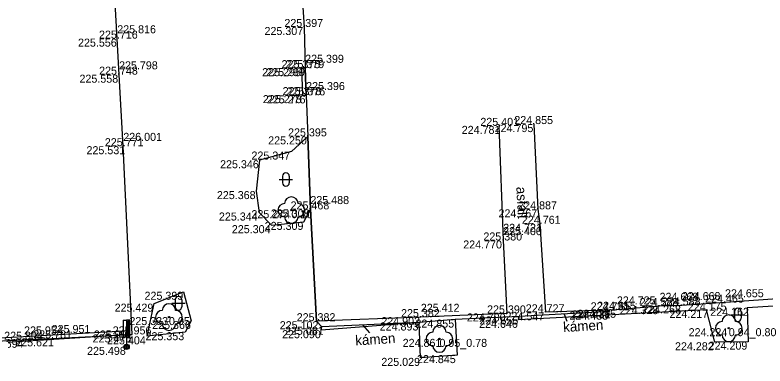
# Model space of a CAD drawing. Extents: x -599516 to -599132, y -1163668 to -1163119.
# Drawn here: x -599371.12 to -599343.03, y -1163301.07 to -1163287.93 of the extents above; entities that cross this region are included whole.
import ezdxf

# ---------------------------------------------------------------- set-up
doc = ezdxf.new("R2010")
doc.units = 0
for name, color, linetype in [('Bod-oznac1', 7, 'Continuous'), ('Bod-oznac2', 7, 'Continuous'), ('Bod-oznac3', 7, 'Continuous'), ('Bod-vyska1', 7, 'Continuous'), ('Bod-vyska2', 7, 'Continuous'), ('Bod-vyska3', 7, 'Continuous'), ('Z_cela-hrobu-dolni-linie', 7, 'Continuous'), ('Z_cela-hrobu-horni-linie', 7, 'Continuous'), ('Z_chodnik', 7, 'Continuous'), ('Z_komunikace', 7, 'Continuous'), ('Z_kultury-znacky', 7, 'Continuous'), ('Z_nove-stromy-prumer-kmene', 7, 'Continuous'), ('Z_obvod-kmene-spodek-ve-vysce1_2m', 7, 'Continuous'), ('Z_ploty-drateny-kovovy', 7, 'Continuous'), ('Z_popis-budov-povrchu', 7, 'Continuous'), ('Z_stromy-kere', 7, 'Continuous'), ('Z_stromy-nove-vysazene', 7, 'Continuous'), ('Z_vol-lin-odkazova-cara', 7, 'Continuous'), ('Z_znacky-ostatni-orientacni-sloupek', 7, 'Continuous'), ('Z_zpevnene-plochy', 7, 'Continuous')]:
    doc.layers.add(name, color=color, linetype=linetype)

msp = doc.modelspace()

# ---------------------------------------------------------------- linework, layer by layer
at = {"layer": 'Bod-oznac1'}
for p, q in [((-599360.296, -1163288.376), (-599360.296, -1163288.376)), ((-599367.294, -1163288.811), (-599367.294, -1163288.811)), ((-599360.396, -1163289.918), (-599360.396, -1163289.918)), ((-599360.254, -1163289.915), (-599360.254, -1163289.915)), ((-599367.227, -1163290.162), (-599367.227, -1163290.162)), ((-599360.357, -1163290.928), (-599360.357, -1163290.928)), ((-599360.217, -1163290.938), (-599360.217, -1163290.938)), ((-599351.672, -1163292.012), (-599351.672, -1163292.012)), ((-599352.997, -1163292.079), (-599352.997, -1163292.079)), ((-599360.159, -1163292.473), (-599360.159, -1163292.473)), ((-599367.068, -1163292.841), (-599367.068, -1163292.841)), ((-599360.77, -1163293.041), (-599360.77, -1163293.041)), ((-599361.959, -1163293.366), (-599361.959, -1163293.366)), ((-599362.091, -1163294.522), (-599362.091, -1163294.522)), ((-599361.981, -1163295.324), (-599361.981, -1163295.324)), ((-599360.772, -1163295.237), (-599360.772, -1163295.237)), ((-599360.059, -1163295.208), (-599360.059, -1163295.208)), ((-599351.524, -1163295.205), (-599351.524, -1163295.205)), ((-599361.51, -1163295.798), (-599361.51, -1163295.798)), ((-599360.301, -1163295.675), (-599360.301, -1163295.675)), ((-599351.443, -1163295.747), (-599351.443, -1163295.747)), ((-599352.836, -1163296.372), (-599352.836, -1163296.372)), ((-599364.813, -1163298.292), (-599364.813, -1163298.292)), ((-599365.91, -1163298.738), (-599365.91, -1163298.738)), ((-599344.524, -1163298.699), (-599344.524, -1163298.699)), ((-599348.862, -1163298.988), (-599348.862, -1163298.988)), ((-599348.848, -1163299.036), (-599348.848, -1163299.036)), ((-599348.575, -1163298.967), (-599348.575, -1163298.967)), ((-599346.976, -1163298.831), (-599346.976, -1163298.831)), ((-599346.144, -1163298.805), (-599346.144, -1163298.805)), ((-599345.212, -1163298.972), (-599345.212, -1163298.972)), ((-599343.698, -1163298.893), (-599343.698, -1163298.893)), ((-599365.357, -1163299.241), (-599365.357, -1163299.241)), ((-599355.921, -1163299.244), (-599355.921, -1163299.244)), ((-599352.704, -1163299.104), (-599352.704, -1163299.104)), ((-599352.237, -1163299.217), (-599352.237, -1163299.217)), ((-599351.241, -1163299.062), (-599351.241, -1163299.062)), ((-599364.526, -1163299.386), (-599364.526, -1163299.386)), ((-599359.83, -1163299.396), (-599359.83, -1163299.396)), ((-599355.98, -1163299.444), (-599355.98, -1163299.444)), ((-599354.629, -1163299.334), (-599354.629, -1163299.334)), ((-599352.256, -1163299.345), (-599352.256, -1163299.345)), ((-599366.818, -1163299.743), (-599366.818, -1163299.743)), ((-599364.753, -1163299.807), (-599364.753, -1163299.807)), ((-599359.652, -1163299.733), (-599359.652, -1163299.733)), ((-599359.635, -1163299.604), (-599359.635, -1163299.604)), ((-599344.383, -1163299.657), (-599344.383, -1163299.657)), ((-599370.786, -1163300.091), (-599370.786, -1163300.091)), ((-599369.751, -1163300.038), (-599369.751, -1163300.038)), ((-599366.735, -1163299.89), (-599366.735, -1163299.89)), ((-599366.174, -1163299.962), (-599366.174, -1163299.962)), ((-599355.222, -1163300.057), (-599355.222, -1163300.057)), ((-599343.658, -1163300.162), (-599343.658, -1163300.162)), ((-599366.944, -1163300.356), (-599366.944, -1163300.356)), ((-599344.905, -1163300.184), (-599344.905, -1163300.184)), ((-599354.559, -1163300.665), (-599354.559, -1163300.665)), ((-599355.933, -1163300.769), (-599355.933, -1163300.769))]:
    msp.add_line(p, q, dxfattribs=at)
at = {"layer": 'Bod-oznac2'}
for p, q in [((-599360.296, -1163288.376), (-599360.296, -1163288.376)), ((-599367.294, -1163288.811), (-599367.294, -1163288.811)), ((-599360.396, -1163289.918), (-599360.396, -1163289.918)), ((-599360.254, -1163289.915), (-599360.254, -1163289.915)), ((-599367.227, -1163290.162), (-599367.227, -1163290.162)), ((-599360.357, -1163290.928), (-599360.357, -1163290.928)), ((-599360.217, -1163290.938), (-599360.217, -1163290.938)), ((-599351.672, -1163292.012), (-599351.672, -1163292.012)), ((-599352.997, -1163292.079), (-599352.997, -1163292.079)), ((-599360.159, -1163292.473), (-599360.159, -1163292.473)), ((-599367.068, -1163292.841), (-599367.068, -1163292.841)), ((-599360.059, -1163295.208), (-599360.059, -1163295.208)), ((-599351.524, -1163295.205), (-599351.524, -1163295.205)), ((-599351.443, -1163295.747), (-599351.443, -1163295.747)), ((-599352.836, -1163296.372), (-599352.836, -1163296.372)), ((-599344.524, -1163298.699), (-599344.524, -1163298.699)), ((-599348.862, -1163298.988), (-599348.862, -1163298.988)), ((-599348.575, -1163298.967), (-599348.575, -1163298.967)), ((-599346.976, -1163298.831), (-599346.976, -1163298.831)), ((-599346.144, -1163298.805), (-599346.144, -1163298.805)), ((-599355.921, -1163299.244), (-599355.921, -1163299.244)), ((-599352.704, -1163299.104), (-599352.704, -1163299.104)), ((-599351.241, -1163299.062), (-599351.241, -1163299.062)), ((-599359.83, -1163299.396), (-599359.83, -1163299.396)), ((-599370.786, -1163300.091), (-599370.786, -1163300.091)), ((-599369.751, -1163300.038), (-599369.751, -1163300.038)), ((-599366.735, -1163299.89), (-599366.735, -1163299.89))]:
    msp.add_line(p, q, dxfattribs=at)
at = {"layer": 'Bod-oznac3'}
for p, q in [((-599367.294, -1163288.811), (-599367.294, -1163288.811)), ((-599360.254, -1163289.915), (-599360.254, -1163289.915)), ((-599367.227, -1163290.162), (-599367.227, -1163290.162)), ((-599360.217, -1163290.938), (-599360.217, -1163290.938)), ((-599367.068, -1163292.841), (-599367.068, -1163292.841)), ((-599360.059, -1163295.208), (-599360.059, -1163295.208)), ((-599352.836, -1163296.372), (-599352.836, -1163296.372)), ((-599344.524, -1163298.699), (-599344.524, -1163298.699)), ((-599348.575, -1163298.967), (-599348.575, -1163298.967)), ((-599346.976, -1163298.831), (-599346.976, -1163298.831)), ((-599346.144, -1163298.805), (-599346.144, -1163298.805)), ((-599355.921, -1163299.244), (-599355.921, -1163299.244)), ((-599370.786, -1163300.091), (-599370.786, -1163300.091)), ((-599369.751, -1163300.038), (-599369.751, -1163300.038))]:
    msp.add_line(p, q, dxfattribs=at)
at = {"layer": 'Z_cela-hrobu-dolni-linie'}
for p, q in [((-599360.217, -1163290.938), (-599360.254, -1163289.915)), ((-599360.159, -1163292.473), (-599360.059, -1163295.208))]:
    msp.add_line(p, q, dxfattribs=at)
for points in [[(-599337.716, -1163298.332), (-599339.375, -1163298.388), (-599341.49, -1163298.479), (-599344.524, -1163298.699), (-599346.144, -1163298.805), (-599346.976, -1163298.831), (-599348.575, -1163298.967), (-599348.862, -1163298.988), (-599351.241, -1163299.062)], [(-599352.704, -1163299.104), (-599355.921, -1163299.244), (-599359.83, -1163299.396)], [(-599373.76, -1163300.233), (-599370.786, -1163300.091), (-599369.751, -1163300.038), (-599366.735, -1163299.89)]]:
    msp.add_lwpolyline(points, dxfattribs=at)
at = {"layer": 'Z_cela-hrobu-horni-linie'}
for points in [[(-599358.085, -1163270.661), (-599361.155, -1163270.895), (-599361.023, -1163273.589), (-599361.023, -1163273.589), (-599361.015, -1163274.729), (-599360.959, -1163276.359), (-599360.959, -1163276.359), (-599360.921, -1163277.44), (-599360.896, -1163277.878), (-599360.835, -1163279.003), (-599360.835, -1163279.003), (-599360.708, -1163280.307), (-599360.708, -1163280.307), (-599360.565, -1163282.313), (-599360.565, -1163282.313), (-599360.49, -1163284.342), (-599360.49, -1163284.342), (-599360.437, -1163286.032), (-599360.407, -1163286.681), (-599360.296, -1163288.376), (-599360.254, -1163289.915), (-599360.217, -1163290.938), (-599360.159, -1163292.473)], [(-599367.068, -1163292.841), (-599367.227, -1163290.162), (-599367.227, -1163290.162), (-599367.294, -1163288.811), (-599367.294, -1163288.811), (-599367.368, -1163287.477)], [(-599331.598, -1163290.945), (-599331.449, -1163294.163), (-599331.449, -1163294.163), (-599331.337, -1163296.61), (-599331.161, -1163297.968), (-599333.927, -1163298.115), (-599333.927, -1163298.115), (-599337.716, -1163298.332), (-599337.716, -1163298.332), (-599339.375, -1163298.388), (-599339.375, -1163298.388), (-599341.49, -1163298.479), (-599341.49, -1163298.479), (-599344.524, -1163298.699), (-599344.524, -1163298.699), (-599346.144, -1163298.805), (-599346.144, -1163298.805), (-599346.976, -1163298.831), (-599346.976, -1163298.831), (-599348.575, -1163298.967), (-599348.575, -1163298.967), (-599348.862, -1163298.988), (-599351.241, -1163299.062), (-599351.443, -1163295.747)], [(-599351.524, -1163295.205), (-599351.672, -1163292.012)], [(-599352.997, -1163292.079), (-599352.836, -1163296.372), (-599352.836, -1163296.372)], [(-599352.836, -1163296.372), (-599352.704, -1163299.104), (-599355.921, -1163299.244), (-599355.921, -1163299.244), (-599359.83, -1163299.396), (-599360.059, -1163295.208), (-599360.059, -1163295.208), (-599360.159, -1163292.473)], [(-599374.034, -1163293.287), (-599373.76, -1163300.233), (-599370.786, -1163300.091), (-599370.786, -1163300.091), (-599369.751, -1163300.038), (-599369.751, -1163300.038), (-599366.735, -1163299.89), (-599367.068, -1163292.841), (-599367.068, -1163292.841), (-599367.068, -1163292.841)]]:
    msp.add_lwpolyline(points, dxfattribs=at)
at = {"layer": 'Z_chodnik'}
for points in [[(-599351.241, -1163299.062), (-599351.443, -1163295.747), (-599351.524, -1163295.205), (-599351.672, -1163292.012)], [(-599352.997, -1163292.079), (-599352.836, -1163296.372), (-599352.704, -1163299.104)]]:
    msp.add_lwpolyline(points, dxfattribs=at)
at = {"layer": 'Z_komunikace'}
for points in [[(-599366.735, -1163299.89), (-599367.068, -1163292.841), (-599367.227, -1163290.162), (-599367.294, -1163288.811), (-599367.368, -1163287.477), (-599367.449, -1163286.118), (-599367.483, -1163285.679), (-599366.879, -1163285.602), (-599365.411, -1163285.358), (-599365.447, -1163282.756), (-599365.824, -1163282.098), (-599366.098, -1163281.601), (-599366.875, -1163281.787), (-599367.63, -1163282.375), (-599367.701, -1163280.792), (-599367.849, -1163278.071), (-599367.991, -1163275.112), (-599367.288, -1163275.117), (-599367.311, -1163274.573), (-599366.256, -1163274.448), (-599365.575, -1163273.958), (-599365.963, -1163272.001), (-599366.67, -1163271.118), (-599368.176, -1163271.31)], [(-599360.407, -1163286.681), (-599360.296, -1163288.376), (-599360.254, -1163289.915), (-599360.396, -1163289.918), (-599360.357, -1163290.928), (-599360.217, -1163290.938), (-599360.159, -1163292.473), (-599360.77, -1163293.041), (-599361.959, -1163293.366), (-599362.091, -1163294.522), (-599361.981, -1163295.324), (-599361.51, -1163295.798), (-599360.301, -1163295.675), (-599360.059, -1163295.208), (-599359.83, -1163299.396)], [(-599366.174, -1163299.962), (-599365.91, -1163298.738), (-599364.813, -1163298.292), (-599364.526, -1163299.386), (-599364.753, -1163299.807), (-599366.174, -1163299.962)], [(-599337.557, -1163298.58), (-599339.305, -1163298.688), (-599341.522, -1163298.76), (-599343.698, -1163298.893)], [(-599343.698, -1163298.893), (-599343.658, -1163300.162), (-599344.905, -1163300.184), (-599345.212, -1163298.972), (-599352.256, -1163299.345), (-599352.237, -1163299.217), (-599354.629, -1163299.334), (-599354.559, -1163300.665), (-599355.933, -1163300.769), (-599355.98, -1163299.444), (-599359.652, -1163299.733), (-599359.635, -1163299.604), (-599359.83, -1163299.396)], [(-599366.735, -1163299.89), (-599374.18, -1163300.364)]]:
    msp.add_lwpolyline(points, dxfattribs=at)
at = {"layer": 'Z_kultury-znacky'}
for p, q in [((-599361.099, -1163293.96), (-599361.099, -1163294.21)), ((-599360.849, -1163293.96), (-599360.849, -1163294.21)), ((-599361.224, -1163294.085), (-599360.724, -1163294.085)), ((-599365.253, -1163298.726), (-599364.753, -1163298.726)), ((-599365.128, -1163298.601), (-599365.128, -1163298.851)), ((-599364.878, -1163298.601), (-599364.878, -1163298.851)), ((-599344.171, -1163299.034), (-599344.171, -1163299.284)), ((-599343.921, -1163299.034), (-599343.921, -1163299.284)), ((-599344.296, -1163299.159), (-599343.796, -1163299.159))]:
    msp.add_line(p, q, dxfattribs=at)
for centre, start, end in [((-599360.974, -1163293.96), 0, 180), ((-599360.974, -1163294.21), 180, 0), ((-599365.003, -1163298.601), 0, 180), ((-599365.003, -1163298.851), 180, 0), ((-599344.046, -1163299.034), 0, 180), ((-599344.046, -1163299.284), 180, 0)]:
    msp.add_arc(centre, 0.125, start, end, dxfattribs=at)
at = {"layer": 'Z_ploty-drateny-kovovy'}
msp.add_lwpolyline([(-599373.895, -1163295.385), (-599373.7, -1163300.135), (-599366.818, -1163299.743)], dxfattribs=at)
at = {"layer": 'Z_stromy-kere'}
for centre in [(-599344.383, -1163299.657), (-599355.222, -1163300.057)]:
    msp.add_circle(centre, 0.025, dxfattribs=at)
for centre, start, end in [((-599344.383, -1163299.407), 0, 180), ((-599355.222, -1163299.807), 0, 180), ((-599344.633, -1163299.657), 90, 270), ((-599344.133, -1163299.657), 270, 90), ((-599355.472, -1163300.057), 90, 270), ((-599354.972, -1163300.057), 270, 90), ((-599344.383, -1163299.907), 180, 0), ((-599355.222, -1163300.307), 180, 0)]:
    msp.add_arc(centre, 0.25, start, end, dxfattribs=at)
at = {"layer": 'Z_stromy-nove-vysazene'}
for centre in [(-599360.772, -1163295.237), (-599365.357, -1163299.241)]:
    msp.add_circle(centre, 0.025, dxfattribs=at)
for centre, start, end in [((-599360.772, -1163294.987), 0, 180), ((-599361.022, -1163295.237), 90, 270), ((-599360.522, -1163295.237), 270, 90), ((-599360.772, -1163295.487), 180, 0), ((-599365.357, -1163298.991), 0, 180), ((-599365.607, -1163299.241), 90, 270), ((-599365.107, -1163299.241), 270, 90), ((-599365.357, -1163299.491), 180, 0)]:
    msp.add_arc(centre, 0.25, start, end, dxfattribs=at)
at = {"layer": 'Z_vol-lin-odkazova-cara'}
for p, q in [((-599350.556, -1163299.128), (-599350.447, -1163299.392)), ((-599358.105, -1163299.537), (-599357.839, -1163299.835))]:
    msp.add_line(p, q, dxfattribs=at)
at = {"layer": 'Z_znacky-ostatni-orientacni-sloupek'}
for p, q in [((-599367.069, -1163299.356), (-599367.069, -1163299.981)), ((-599367.069, -1163299.356), (-599366.944, -1163299.356)), ((-599367.069, -1163299.981), (-599366.944, -1163299.981)), ((-599366.944, -1163299.981), (-599366.944, -1163300.256))]:
    msp.add_line(p, q, dxfattribs=at)
for points in [[(-599366.944, -1163299.981), (-599366.819, -1163299.981), (-599366.819, -1163299.356), (-599366.944, -1163299.356)], [(-599366.902, -1163299.938), (-599366.861, -1163299.938), (-599366.861, -1163299.399), (-599366.902, -1163299.399)]]:
    msp.add_lwpolyline(points, close=True, dxfattribs=at)
for radius in [0.1, 0.065, 0.03]:
    msp.add_circle((-599366.944, -1163300.356), radius, dxfattribs=at)
at = {"layer": 'Z_zpevnene-plochy'}
for points in [[(-599360.254, -1163289.915), (-599360.396, -1163289.918), (-599360.357, -1163290.928), (-599360.217, -1163290.938)], [(-599348.862, -1163298.988), (-599348.848, -1163299.036), (-599352.237, -1163299.217)], [(-599354.629, -1163299.334), (-599355.98, -1163299.444), (-599359.635, -1163299.604)]]:
    msp.add_lwpolyline(points, dxfattribs=at)

# ---------------------------------------------------------------- texts
at = {"layer": 'Bod-vyska1'}
for s, p in [('225.307', (-599361.777, -1163288.676)), ('225.556', (-599368.764, -1163289.111)), ('225.295', (-599361.866, -1163290.218)), ('225.299', (-599361.713, -1163290.215)), ('225.558', (-599368.709, -1163290.462)), ('225.278', (-599361.84, -1163291.228)), ('225.276', (-599361.689, -1163291.238)), ('224.795', (-599353.155, -1163292.312)), ('224.781', (-599354.388, -1163292.379)), ('225.250', (-599361.639, -1163292.773)), ('225.531', (-599368.446, -1163293.141)), ('225.347', (-599362.265, -1163293.341)), ('225.346', (-599363.441, -1163293.666)), ('225.368', (-599363.561, -1163294.822)), ('225.344', (-599363.485, -1163295.624)), ('225.274', (-599362.267, -1163295.537)), ('225.308', (-599361.539, -1163295.508)), ('224.767', (-599353.009, -1163295.505)), ('225.304', (-599363.001, -1163296.098)), ('225.309', (-599361.769, -1163295.975)), ('224.721', (-599352.834, -1163296.047)), ('224.770', (-599354.331, -1163296.672)), ('225.399', (-599366.272, -1163298.592)), ('225.429', (-599367.392, -1163299.038)), ('224.175', (-599345.915, -1163298.999)), ('224.433', (-599350.352, -1163299.336)), ('224.431', (-599350.262, -1163299.288)), ('224.395', (-599350.056, -1163299.267)), ('224.328', (-599348.469, -1163299.131)), ('224.268', (-599347.625, -1163299.105)), ('224.217', (-599346.603, -1163299.272)), ('224.162', (-599345.076, -1163299.193)), ('225.333', (-599366.839, -1163299.541)), ('224.902', (-599357.401, -1163299.544)), ('224.700', (-599354.195, -1163299.404)), ('224.655', (-599353.718, -1163299.517)), ('224.547', (-599352.747, -1163299.362)), ('225.366', (-599365.985, -1163299.686)), ('225.102', (-599361.206, -1163299.696)), ('225.081', (-599361.011, -1163299.904)), ('224.893', (-599357.461, -1163299.744)), ('224.855', (-599356.122, -1163299.634)), ('224.646', (-599353.737, -1163299.645)), ('225.991', (-599368.173, -1163300.043)), ('225.353', (-599366.235, -1163300.107)), ('225.090', (-599361.118, -1163300.033)), ('224.224', (-599345.887, -1163299.957)), ('225.694', (-599372.256, -1163300.391)), ('225.621', (-599371.117, -1163300.338)), ('225.476', (-599368.218, -1163300.19)), ('225.404', (-599367.676, -1163300.262)), ('224.861', (-599356.6, -1163300.357)), ('224.209', (-599345.138, -1163300.462)), ('225.498', (-599368.425, -1163300.656)), ('224.282', (-599346.398, -1163300.484)), ('224.845', (-599356.063, -1163300.965)), ('225.029', (-599357.401, -1163301.069))]:
    msp.add_text(s, height=0.3, dxfattribs=at).set_placement(p)
at = {"layer": 'Bod-vyska2'}
for s, p in [('225.397', (-599361.032, -1163288.376)), ('225.716', (-599367.978, -1163288.811)), ('225.375', (-599361.138, -1163289.918)), ('225.379', (-599360.99, -1163289.915)), ('225.748', (-599367.974, -1163290.162)), ('225.378', (-599361.099, -1163290.928)), ('225.376', (-599360.953, -1163290.938)), ('224.855', (-599352.418, -1163292.012)), ('225.401', (-599353.69, -1163292.079)), ('225.395', (-599360.894, -1163292.473)), ('225.771', (-599367.759, -1163292.841)), ('225.468', (-599360.8, -1163295.208)), ('224.887', (-599352.271, -1163295.205)), ('224.761', (-599352.133, -1163295.747)), ('225.380', (-599353.576, -1163296.372)), ('224.465', (-599345.27, -1163298.699)), ('224.727', (-599351.989, -1163299.062)), ('224.731', (-599349.557, -1163298.988)), ('224.655', (-599349.316, -1163298.967)), ('224.588', (-599347.722, -1163298.831)), ('224.588', (-599346.89, -1163298.805)), ('225.382', (-599356.662, -1163299.244)), ('225.390', (-599353.438, -1163299.104)), ('225.382', (-599360.571, -1163299.396)), ('225.956', (-599367.464, -1163299.89)), ('225.804', (-599371.531, -1163300.091)), ('225.781', (-599370.441, -1163300.038))]:
    msp.add_text(s, height=0.3, dxfattribs=at).set_placement(p)
at = {"layer": 'Bod-vyska3'}
for s, p in [('225.816', (-599367.294, -1163288.611)), ('225.399', (-599360.254, -1163289.715)), ('225.798', (-599367.227, -1163289.962)), ('225.396', (-599360.217, -1163290.738)), ('226.001', (-599367.068, -1163292.641)), ('225.488', (-599360.059, -1163295.008)), ('225.400', (-599352.836, -1163296.172)), ('224.655', (-599344.524, -1163298.499)), ('224.725', (-599348.575, -1163298.767)), ('224.668', (-599346.976, -1163298.631)), ('224.668', (-599346.144, -1163298.605)), ('225.412', (-599355.921, -1163299.044)), ('225.954', (-599370.786, -1163299.891)), ('225.951', (-599369.751, -1163299.838))]:
    msp.add_text(s, height=0.3, dxfattribs=at).set_placement(p)
at = {"layer": 'Z_nove-stromy-prumer-kmene'}
for s, p in [('0.10', (-599360.772, -1163295.537)), ('0.05', (-599365.357, -1163299.541))]:
    msp.add_text(s, height=0.3, dxfattribs=at).set_placement(p)
at = {"layer": 'Z_obvod-kmene-spodek-ve-vysce1_2m'}
for s, p in [('0.94_0.80', (-599344.383, -1163299.957)), ('0.95_0.78', (-599355.222, -1163300.357))]:
    msp.add_text(s, height=0.3, dxfattribs=at).set_placement(p)
at = {"layer": 'Z_popis-budov-povrchu'}
for s, rotation, p in [('asfalt', 273.4503, (-599352.347, -1163294.369)), ('kámen', 3.4503, (-599350.577, -1163299.804)), ('kámen', 3.4503, (-599358.366, -1163300.304))]:
    msp.add_text(s, height=0.375, rotation=rotation, dxfattribs=at).set_placement(p)

doc.saveas('drawing.dxf')
